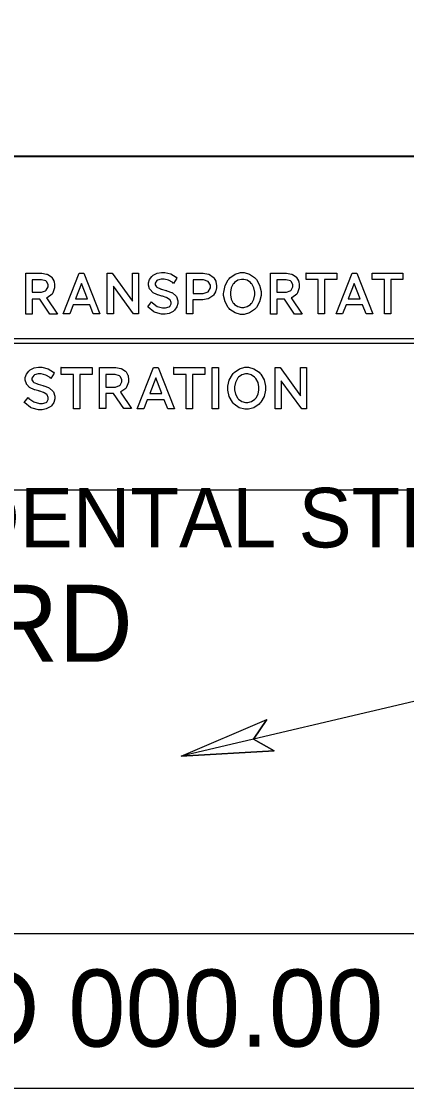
# Model space of a CAD drawing. Extents: x -0.5 to 19.9, y 5.2 to 17.3.
# Drawn here: x 6.132 to 6.731, y 5.937 to 7.599 of the extents above; entities that cross this region are included whole.
import ezdxf

# ---------------------------------------------------------------- set-up
doc = ezdxf.new("R2010")
doc.units = 0
for name, color, linetype in [('BORD-LINE', 7, 'Continuous'), ('DETL-DIMS', 7, 'Continuous'), ('DETL-NOTE', 7, 'Continuous'), ('MSHA-LOGO', 7, 'Continuous'), ('TTLB-TEXT', 7, 'Continuous'), ('USER-BORD', 7, 'Continuous'), ('USER-LINE', 7, 'Continuous')]:
    doc.layers.add(name, color=color, linetype=linetype)

msp = doc.modelspace()

# ---------------------------------------------------------------- linework, layer by layer
at = {"layer": 'BORD-LINE'}
msp.add_line((7.7685, 7.3883), (0.3943, 7.3883), dxfattribs=at)
at = {"layer": 'DETL-DIMS'}
for p, q in [((7.1787, 6.6431), (6.3803, 6.4551)), ((6.3803, 6.4551), (6.5137, 6.5124)), ((6.4932, 6.4817), (6.5137, 6.5124)), ((6.5253, 6.4633), (6.4932, 6.4817)), ((6.3803, 6.4551), (6.5253, 6.4633))]:
    msp.add_line(p, q, dxfattribs=at)
msp.add_lwpolyline([(6.5253, 6.4633), (6.3803, 6.4551), (6.5137, 6.5124), (6.4932, 6.4817)], close=True, dxfattribs=at)
at = {"layer": 'MSHA-LOGO'}
for points in [[(6.1386, 7.1437), (6.1386, 7.2072), (6.1608, 7.2072), (6.1636, 7.2072), (6.1711, 7.2058), (6.1719, 7.2055), (6.1727, 7.2053), (6.1784, 7.2014), (6.1788, 7.2009), (6.1792, 7.2005), (6.1822, 7.1953), (6.1824, 7.1947), (6.1827, 7.1941), (6.1834, 7.1889), (6.1834, 7.1871), (6.1834, 7.1842), (6.1807, 7.1764), (6.1801, 7.1756), (6.1795, 7.1748), (6.1719, 7.169), (6.171, 7.1687), (6.188, 7.1434), (6.1759, 7.1434), (6.1605, 7.1667), (6.1484, 7.1667), (6.1484, 7.1434), (6.1386, 7.1434)], [(6.1484, 7.197), (6.1484, 7.1776), (6.1612, 7.1776), (6.1633, 7.1776), (6.1694, 7.1798), (6.17, 7.1802), (6.1705, 7.1806), (6.1733, 7.186), (6.1733, 7.1878), (6.1733, 7.1895), (6.1708, 7.1943), (6.1703, 7.1947), (6.1698, 7.1951), (6.1631, 7.197), (6.1608, 7.197)], [(6.2217, 7.2075), (6.2292, 7.2075), (6.2541, 7.144), (6.2436, 7.144), (6.2381, 7.1582), (6.2125, 7.1582), (6.207, 7.144), (6.1968, 7.144)], [(6.3064, 7.1437), (6.275, 7.1871), (6.275, 7.1437), (6.2655, 7.1437), (6.2655, 7.2072), (6.2731, 7.2072), (6.3045, 7.1638), (6.3045, 7.2072), (6.314, 7.2072), (6.314, 7.1437)], [(6.3627, 7.1661), (6.3624, 7.1664), (6.3583, 7.1691), (6.3578, 7.1694), (6.3573, 7.1695), (6.3516, 7.1712), (6.351, 7.1713), (6.3503, 7.1715), (6.3441, 7.1734), (6.3434, 7.1736), (6.3428, 7.1739), (6.337, 7.1766), (6.3366, 7.1769), (6.3361, 7.1773), (6.332, 7.1816), (6.3316, 7.1822), (6.3313, 7.1828), (6.3297, 7.1885), (6.3297, 7.1904), (6.3297, 7.1921), (6.3312, 7.1973), (6.3348, 7.2023), (6.3359, 7.2032), (6.3369, 7.2041), (6.343, 7.2072), (6.3497, 7.2085), (6.3519, 7.2085), (6.3551, 7.2085), (6.3645, 7.2062), (6.3726, 7.2009), (6.3739, 7.1993), (6.3686, 7.1914), (6.3674, 7.1925), (6.3607, 7.1963), (6.3539, 7.198), (6.3516, 7.198), (6.3495, 7.198), (6.3437, 7.1963), (6.3431, 7.196), (6.3425, 7.1957), (6.3398, 7.1917), (6.3398, 7.1904), (6.3398, 7.1892), (6.342, 7.1858), (6.3424, 7.1855), (6.3428, 7.1852), (6.3483, 7.1827), (6.349, 7.1825), (6.3496, 7.1824), (6.3568, 7.1805), (6.3575, 7.1802), (6.3582, 7.18), (6.3653, 7.1773), (6.366, 7.1769), (6.3667, 7.1766), (6.3721, 7.172), (6.3726, 7.1713), (6.373, 7.1707), (6.3752, 7.1642), (6.3752, 7.1621), (6.3752, 7.1602), (6.3736, 7.1546), (6.37, 7.1495), (6.369, 7.1486), (6.3679, 7.1477), (6.3619, 7.1446), (6.3556, 7.1434), (6.3536, 7.1434), (6.3499, 7.1434), (6.3403, 7.1461), (6.3392, 7.1467), (6.338, 7.1472), (6.329, 7.1541), (6.3284, 7.1549), (6.3343, 7.1624), (6.3356, 7.161), (6.3431, 7.1556), (6.3515, 7.1532), (6.3542, 7.1532), (6.3562, 7.1532), (6.3617, 7.1549), (6.3621, 7.1552), (6.3626, 7.1555), (6.365, 7.1595), (6.365, 7.1608), (6.3649, 7.1614), (6.3631, 7.1657)], [(6.3889, 7.1437), (6.3889, 7.2072), (6.4118, 7.2072), (6.4148, 7.2072), (6.4228, 7.2058), (6.4236, 7.2055), (6.4244, 7.2052), (6.4304, 7.2011), (6.4308, 7.2006), (6.4312, 7.2001), (6.4342, 7.1946), (6.4344, 7.194), (6.4346, 7.1935), (6.4354, 7.1882), (6.4354, 7.1865), (6.4354, 7.1846), (6.4343, 7.1795), (6.4341, 7.1789), (6.4338, 7.1783), (6.4306, 7.1728), (6.4301, 7.1723), (6.4297, 7.1718), (6.4234, 7.1677), (6.4226, 7.1674), (6.4218, 7.1671), (6.4141, 7.1657), (6.4115, 7.1657), (6.3984, 7.1657), (6.3984, 7.144), (6.3889, 7.144)], [(6.3991, 7.197), (6.3991, 7.1756), (6.4121, 7.1756), (6.4147, 7.1756), (6.4224, 7.1783), (6.4259, 7.1844), (6.4259, 7.1865), (6.4259, 7.1884), (6.4226, 7.1943), (6.4152, 7.197), (6.4128, 7.197)], [(6.455, 7.1986), (6.4564, 7.2002), (6.4643, 7.2057), (6.4728, 7.2082), (6.4756, 7.2082), (6.4784, 7.2082), (6.4869, 7.2059), (6.4948, 7.2005), (6.4962, 7.199), (6.4976, 7.1974), (6.5026, 7.1885), (6.5048, 7.1788), (6.5048, 7.1756), (6.5048, 7.1724), (6.5026, 7.1628), (6.4976, 7.1538), (6.4962, 7.1522), (6.4948, 7.1507), (6.4869, 7.1453), (6.4784, 7.143), (6.4756, 7.143), (6.4728, 7.143), (6.4643, 7.1453), (6.4564, 7.1507), (6.455, 7.1522), (6.4536, 7.1538), (6.4487, 7.1627), (6.4465, 7.1724), (6.4465, 7.1756), (6.4466, 7.1779), (6.4488, 7.1882), (6.4536, 7.1971)], [(6.4625, 7.1598), (6.4634, 7.1587), (6.4686, 7.1551), (6.4741, 7.1536), (6.476, 7.1536), (6.4778, 7.1536), (6.4833, 7.1551), (6.4885, 7.1587), (6.4894, 7.1598), (6.4903, 7.1608), (6.4935, 7.1667), (6.4949, 7.1734), (6.4949, 7.1756), (6.4949, 7.1778), (6.4935, 7.1845), (6.4903, 7.1904), (6.4894, 7.1914), (6.4885, 7.1925), (6.4833, 7.1961), (6.4778, 7.1976), (6.476, 7.1976), (6.4742, 7.1976), (6.4688, 7.1961), (6.4635, 7.1925), (6.4625, 7.1914), (6.4616, 7.1904), (6.4584, 7.1845), (6.457, 7.1778), (6.457, 7.1756), (6.457, 7.1734), (6.4583, 7.1667), (6.4616, 7.1608)], [(6.5195, 7.1437), (6.5195, 7.2072), (6.5417, 7.2072), (6.5445, 7.2072), (6.552, 7.2058), (6.5529, 7.2055), (6.5536, 7.2053), (6.5593, 7.2014), (6.5597, 7.2009), (6.5601, 7.2005), (6.5631, 7.1953), (6.5633, 7.1947), (6.5635, 7.1941), (6.5643, 7.1889), (6.5643, 7.1871), (6.5643, 7.1842), (6.5616, 7.1764), (6.561, 7.1756), (6.5605, 7.1748), (6.5528, 7.169), (6.5519, 7.1687), (6.5689, 7.1434), (6.5568, 7.1434), (6.5414, 7.1667), (6.5293, 7.1667), (6.5293, 7.1434), (6.5195, 7.1434)], [(6.5293, 7.197), (6.5293, 7.1776), (6.5421, 7.1776), (6.5443, 7.1776), (6.5503, 7.1798), (6.5509, 7.1802), (6.5514, 7.1806), (6.5542, 7.186), (6.5542, 7.1878), (6.5542, 7.1895), (6.5517, 7.1943), (6.5512, 7.1947), (6.5507, 7.1951), (6.544, 7.197), (6.5417, 7.197)], [(6.5745, 7.2075), (6.6226, 7.2075), (6.6226, 7.1973), (6.6036, 7.1973), (6.6036, 7.144), (6.5938, 7.144), (6.5938, 7.1973), (6.5748, 7.1973), (6.5748, 7.2075)], [(6.6465, 7.2075), (6.654, 7.2075), (6.6789, 7.144), (6.6684, 7.144), (6.6628, 7.1582), (6.637, 7.1582), (6.6314, 7.144), (6.6216, 7.144)], [(6.6775, 7.2075), (6.7257, 7.2075), (6.7257, 7.1973), (6.7067, 7.1973), (6.7067, 7.144), (6.6969, 7.144), (6.6969, 7.1973), (6.6779, 7.1973), (6.6779, 7.2075)], [(6.2161, 7.1674), (6.2348, 7.1674), (6.2253, 7.1914)], [(6.6406, 7.1674), (6.6592, 7.1674), (6.6497, 7.1914)], [(4.7668, 7.1057), (6.8835, 7.1057), (6.8835, 7.0979), (4.7668, 7.0979)], [(6.1718, 7.0181), (6.1714, 7.0185), (6.1672, 7.0211), (6.1667, 7.0214), (6.1661, 7.0215), (6.1603, 7.0235), (6.1596, 7.0236), (6.159, 7.0238), (6.1526, 7.0256), (6.152, 7.0258), (6.1513, 7.0261), (6.1455, 7.0287), (6.1449, 7.0291), (6.1444, 7.0294), (6.1401, 7.034), (6.1398, 7.0345), (6.1395, 7.0351), (6.1379, 7.0409), (6.1379, 7.0429), (6.1379, 7.0446), (6.1395, 7.0499), (6.1433, 7.0548), (6.1443, 7.0557), (6.1453, 7.0566), (6.1515, 7.0596), (6.1583, 7.0609), (6.1606, 7.0609), (6.1638, 7.0609), (6.1733, 7.0585), (6.1816, 7.0531), (6.183, 7.0515), (6.1775, 7.0435), (6.1763, 7.0446), (6.1696, 7.0486), (6.1626, 7.0503), (6.1603, 7.0503), (6.1581, 7.0503), (6.1522, 7.0487), (6.1516, 7.0483), (6.1511, 7.048), (6.1481, 7.0439), (6.1481, 7.0425), (6.1481, 7.0413), (6.1503, 7.0378), (6.1507, 7.0374), (6.1511, 7.0371), (6.1567, 7.0347), (6.1574, 7.0345), (6.1581, 7.0344), (6.1652, 7.0322), (6.166, 7.032), (6.1668, 7.0317), (6.174, 7.029), (6.1747, 7.0287), (6.1753, 7.0284), (6.1809, 7.0236), (6.1814, 7.023), (6.1818, 7.0223), (6.1839, 7.0158), (6.1839, 7.0136), (6.1839, 7.0118), (6.1823, 7.006), (6.1786, 7.0007), (6.1775, 6.9998), (6.1765, 6.999), (6.1704, 6.9958), (6.164, 6.9944), (6.1619, 6.9944), (6.1582, 6.9944), (6.1484, 6.997), (6.1472, 6.9976), (6.146, 6.9982), (6.1369, 7.0051), (6.1363, 7.0059), (6.1424, 7.0136), (6.1436, 7.0121), (6.1513, 7.0067), (6.1599, 7.0043), (6.1628, 7.0043), (6.1648, 7.0043), (6.1703, 7.0059), (6.1708, 7.0063), (6.1713, 7.0066), (6.1737, 7.0107), (6.1737, 7.012), (6.1737, 7.0136), (6.1721, 7.0178)], [(6.1932, 7.0602), (6.2418, 7.0602), (6.2418, 7.0496), (6.2226, 7.0496), (6.2226, 6.996), (6.2127, 6.996), (6.2127, 7.0496), (6.1935, 7.0496), (6.1935, 7.0602)], [(6.2533, 6.996), (6.2533, 7.0602), (6.2759, 7.0602), (6.2787, 7.0602), (6.2863, 7.0588), (6.2871, 7.0586), (6.2879, 7.0584), (6.2938, 7.0546), (6.2942, 7.0541), (6.2946, 7.0536), (6.2975, 7.0483), (6.2977, 7.0477), (6.2978, 7.0471), (6.2986, 7.042), (6.2986, 7.0403), (6.2986, 7.0374), (6.2956, 7.0295), (6.2951, 7.0287), (6.2945, 7.0279), (6.2868, 7.0223), (6.2858, 7.022), (6.3031, 6.9963), (6.291, 6.9963), (6.2753, 7.0197), (6.2631, 7.0197), (6.2631, 6.9963), (6.2533, 6.9963)], [(6.2631, 7.0496), (6.2631, 7.03), (6.2759, 7.03), (6.2782, 7.03), (6.2843, 7.0322), (6.2849, 7.0326), (6.2854, 7.0331), (6.2881, 7.0383), (6.2881, 7.04), (6.2881, 7.0418), (6.2857, 7.0466), (6.2852, 7.047), (6.2847, 7.0474), (6.2779, 7.0496), (6.2756, 7.0496)], [(6.3373, 7.0602), (6.3449, 7.0602), (6.3702, 6.996), (6.3597, 6.996), (6.3539, 7.0101), (6.3277, 7.0101), (6.3223, 6.996), (6.312, 6.996)], [(6.3686, 7.0602), (6.4172, 7.0602), (6.4172, 7.0496), (6.398, 7.0496), (6.398, 6.996), (6.3881, 6.996), (6.3881, 7.0496), (6.3689, 7.0496), (6.3689, 7.0602)], [(6.4287, 7.0602), (6.4386, 7.0602), (6.4386, 6.996), (6.4287, 6.996)], [(6.4616, 7.0512), (6.463, 7.0528), (6.4711, 7.0584), (6.4795, 7.0609), (6.4823, 7.0609), (6.4852, 7.0609), (6.4937, 7.0585), (6.5017, 7.0531), (6.5031, 7.0515), (6.5044, 7.05), (6.5095, 7.041), (6.5117, 7.0313), (6.5117, 7.0281), (6.5117, 7.0249), (6.5096, 7.0153), (6.5045, 7.0063), (6.5031, 7.0047), (6.5017, 7.0031), (6.4935, 6.9976), (6.4851, 6.9953), (6.4823, 6.9953), (6.4795, 6.9953), (6.4709, 6.9977), (6.4629, 7.0031), (6.4616, 7.0047), (6.4601, 7.0062), (6.4551, 7.0152), (6.4529, 7.0249), (6.4529, 7.0281), (6.4529, 7.0313), (6.4551, 7.0408), (6.4601, 7.0497)], [(6.4689, 7.012), (6.4699, 7.011), (6.4751, 7.0074), (6.4805, 7.0059), (6.4823, 7.0059), (6.4842, 7.0059), (6.4898, 7.0074), (6.4951, 7.011), (6.4961, 7.012), (6.497, 7.0131), (6.5002, 7.0191), (6.5015, 7.0258), (6.5015, 7.0281), (6.5015, 7.0303), (6.5001, 7.037), (6.4967, 7.0431), (6.4958, 7.0441), (6.4948, 7.0452), (6.4895, 7.0488), (6.4841, 7.0503), (6.4823, 7.0503), (6.4805, 7.0503), (6.475, 7.0488), (6.4698, 7.0452), (6.4689, 7.0441), (6.468, 7.0431), (6.4649, 7.0371), (6.4635, 7.0303), (6.4635, 7.0281), (6.4635, 7.0258), (6.4649, 7.0191), (6.468, 7.0131)], [(6.568, 6.996), (6.5363, 7.0397), (6.5363, 6.996), (6.5267, 6.996), (6.5267, 7.0602), (6.5344, 7.0602), (6.5661, 7.0162), (6.5661, 7.0602), (6.5756, 7.0602), (6.5756, 6.996)], [(6.3315, 7.0197), (6.3504, 7.0197), (6.3408, 7.0441)]]:
    msp.add_lwpolyline(points, close=True, dxfattribs=at)
at = {"layer": 'TTLB-TEXT'}
msp.add_line((7.7685, 7.3883), (0.3943, 7.3883), dxfattribs=at)
msp.add_lwpolyline([(0.3943, 16.2906), (7.7685, 16.2906), (7.7685, 5.9375), (0.3943, 5.9375)], close=True, dxfattribs=at)
at = {"layer": 'USER-BORD'}
for p, q in [((7.7685, 7.3883), (0.3943, 7.3883)), ((3.2956, 6.1793), (7.7685, 6.1793)), ((6.4001, 6.0629), (6.4001, 6.0629))]:
    msp.add_line(p, q, dxfattribs=at)
at = {"layer": 'USER-LINE'}
msp.add_lwpolyline([(7.0197, 6.8692), (4.0486, 6.8692), (4.0486, 7.3899), (7.0197, 7.3899)], close=True, dxfattribs=at)

# ---------------------------------------------------------------- texts
at = {"layer": 'DETL-NOTE'}
msp.add_text('STANDARDS FOR HIGHWAYS AND INCIDENTAL STRUCTURES', height=0.09269, dxfattribs=at).set_placement((3.6914, 6.7803))
at = {"layer": 'TTLB-TEXT'}
for s, height, p in [('STANDARDS FOR HIGHWAYS AND INCIDENTAL STRUCTURES', 0.09269, (3.6913, 6.7802)), ('STANDARDS FOR HIGHWAYS AND INCIDENTAL STRUCTURES', 0.09269, (3.6914, 6.7803)), ('SAMPLE STANDARD', 0.12, (4.727, 6.6021)), ('MD 000.00', 0.12, (5.9104, 6.0029))]:
    msp.add_text(s, height=height, dxfattribs=at).set_placement(p)

doc.saveas('drawing.dxf')
